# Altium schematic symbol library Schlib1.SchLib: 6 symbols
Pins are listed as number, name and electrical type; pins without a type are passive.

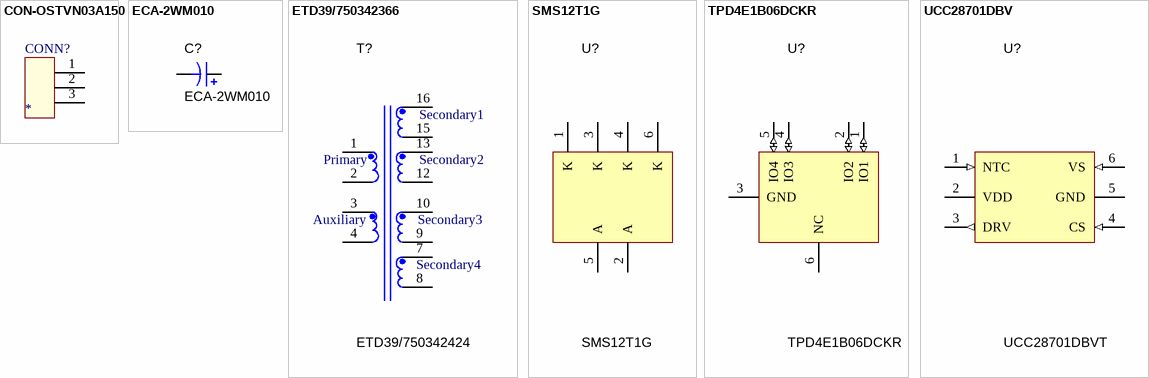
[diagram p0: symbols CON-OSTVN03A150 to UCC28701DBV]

## CON-OSTVN03A150
designator CONN?
CONN TERM BLOCK 2.54MM 3POS PCB; Manufacturer: On Shore Technology Inc; PartNumber: OSTVN03A150; SymbolCreator: x0120606; CompType: Terminal Block
footprint TB_OSTVN03A150_3P
pins: 1, 2, 3

## ECA-2WM010
designator C?
CAP ALUM 1.0UF 450V 20% RADIAL; Manufacturer: Panasonic Electronic Components; Value: 1UF
footprint Radial-CAP_8mmDia _12.5 (Radial, Can)
pins: 1 +, 2 -

## ETD39/750342366
designator T?, comment ETD39/750342424
Transformer,   TH; Manufacturer: wurth elektronik; SymbolCreator: a0411947; U/M: EA
footprint XFORMER_ETD39
pins: 1, 2, 3, 4, 5 hidden, 6 hidden, 7, 8, 9, 10, 11 hidden, 12, 13, 14 hidden, 15, 16

## SMS12T1G
designator U?
TVS DIODE 12VWM 23VC SC74-6; Manufacturer: TI; U/M: EA; Description: TVS DIODE 5.5VWM 14.5VC SC70-6
pins: 1 K, 2 A, 3 K, 4 K, 5 A, 6 K

## TPD4E1B06DCKR
designator U?
TVS DIODE 5.5VWM 14.5VC SC70-6; Manufacturer: TI; U/M: EA
pins: 1 IO1 (io), 2 IO2 (io), 3 GND (power), 4 IO3 (io), 5 IO4 (io), 6 NC

## UCC28701DBV
designator U?, comment UCC28701DBVT
IC, Constant Voltage, Constant Current PWM With Primary Side Regulation; Manufacturer: TI; SymbolCreator: a0411947; CompType: Transformer; Value: UCC2871xDBV; U/M: EA
footprint DBV-6 (Footprint not found)
pins: 1 NTC (in), 2 VDD (power), 3 DRV (out), 4 CS (in), 5 GND (power), 6 VS (in)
